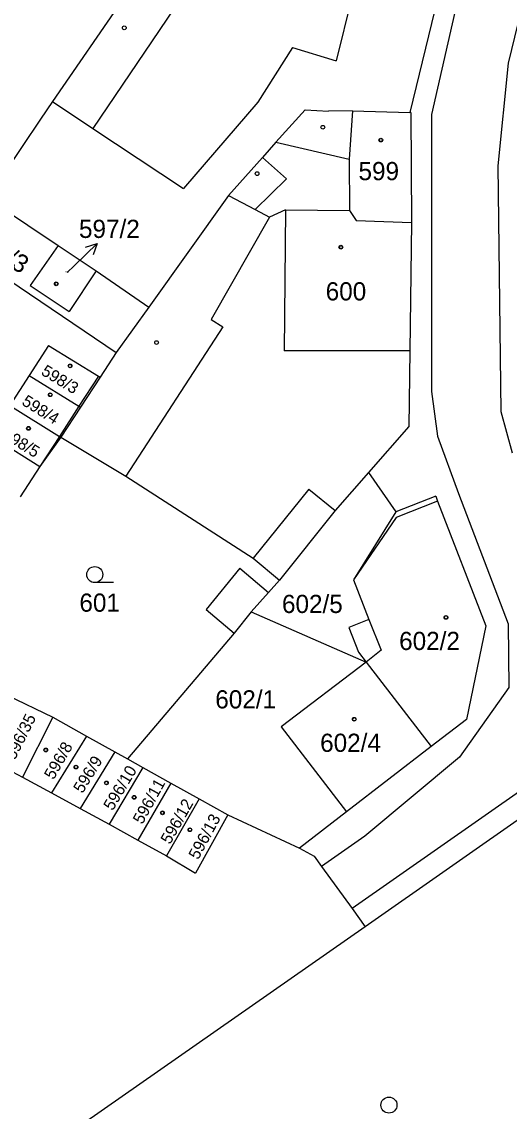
# Model space of a CAD drawing. Extents: x -593183 to -588034, y -1130415 to -1124994.
# Drawn here: x -591118.2 to -591072.6, y -1128787.1 to -1128685.3 of the extents above; entities that cross this region are included whole.
import ezdxf

# ---------------------------------------------------------------- set-up
doc = ezdxf.new("R2010")
doc.units = 0
for name, color, linetype in [('Vrstva 1', 7, 'Continuous'), ('Vrstva 16', 7, 'Continuous'), ('Vrstva 18', 7, 'Continuous'), ('Vrstva 19', 7, 'Continuous'), ('Vrstva 25', 7, 'Continuous'), ('Vrstva 4', 7, 'Continuous')]:
    doc.layers.add(name, color=color, linetype=linetype)

msp = doc.modelspace()

# ---------------------------------------------------------------- linework, layer by layer
at = {"layer": 'Vrstva 1'}
for p, q in [((-591074.25, -1128662.36), (-591081.86, -1128693.73)), ((-591105.59, -1128678.63), (-591115.3, -1128692.72)), ((-591115.3, -1128692.72), (-591116.41, -1128694.38)), ((-591116.41, -1128694.38), (-591119.84, -1128699.47)), ((-591091.64, -1128693.48), (-591094.38, -1128696.53)), ((-591091.64, -1128693.48), (-591089.48, -1128693.63)), ((-591087.23, -1128693.59), (-591089.48, -1128693.63)), ((-591087.23, -1128693.59), (-591081.86, -1128693.73)), ((-591081.76, -1128693.73), (-591081.86, -1128693.73)), ((-591081.76, -1128693.73), (-591081.71, -1128704.03)), ((-591094.38, -1128696.53), (-591095.65, -1128697.95)), ((-591095.65, -1128697.95), (-591098.83, -1128701.49)), ((-591098.83, -1128701.49), (-591106.26, -1128711.94)), ((-591098.83, -1128701.49), (-591096.34, -1128702.82)), ((-591121.38, -1128701.75), (-591114.77, -1128706.18)), ((-591096.34, -1128702.82), (-591094.99, -1128703.54)), ((-591093.49, -1128702.85), (-591094.99, -1128703.54)), ((-591093.49, -1128702.85), (-591087.51, -1128702.91)), ((-591087.51, -1128702.91), (-591086.87, -1128703.83)), ((-591086.87, -1128703.83), (-591081.71, -1128704.03)), ((-591081.71, -1128704.03), (-591081.85, -1128716.01)), ((-591124.56, -1128705.88), (-591109.32, -1128716.18)), ((-591114.77, -1128706.18), (-591117.38, -1128709.9)), ((-591114.77, -1128706.18), (-591111.2, -1128708.55)), ((-591111.2, -1128708.55), (-591113.74, -1128712.33)), ((-591111.2, -1128708.55), (-591106.26, -1128711.94)), ((-591117.38, -1128709.9), (-591113.74, -1128712.33)), ((-591106.26, -1128711.94), (-591109.32, -1128716.18)), ((-591115.66, -1128715.52), (-591117.48, -1128718.33)), ((-591115.66, -1128715.52), (-591110.99, -1128718.39)), ((-591109.32, -1128716.18), (-591110.82, -1128718.49)), ((-591081.85, -1128716.01), (-591081.96, -1128723.09)), ((-591117.48, -1128718.33), (-591119.28, -1128721.14)), ((-591117.48, -1128718.33), (-591112.81, -1128721.2)), ((-591110.82, -1128718.49), (-591112.67, -1128721.3)), ((-591110.99, -1128718.39), (-591110.82, -1128718.49)), ((-591119.28, -1128721.14), (-591114.64, -1128724.02)), ((-591112.67, -1128721.3), (-591114.51, -1128724.1)), ((-591112.81, -1128721.2), (-591112.67, -1128721.3)), ((-591081.96, -1128723.09), (-591085.71, -1128727.38)), ((-591121.09, -1128723.95), (-591116.47, -1128726.84)), ((-591114.51, -1128724.1), (-591116.47, -1128726.84)), ((-591114.64, -1128724.02), (-591114.51, -1128724.1)), ((-591114.51, -1128724.1), (-591108.43, -1128727.75)), ((-591116.47, -1128726.84), (-591118.3, -1128729.66)), ((-591108.43, -1128727.75), (-591096.5, -1128735.39)), ((-591085.71, -1128727.38), (-591088.84, -1128730.94)), ((-591085.71, -1128727.38), (-591083.17, -1128731.06)), ((-591079.44, -1128729.61), (-591083.17, -1128731.06)), ((-591079.44, -1128729.61), (-591079.26, -1128730.07)), ((-591088.84, -1128730.94), (-591094.06, -1128737.47)), ((-591083.17, -1128731.06), (-591087.14, -1128737.42)), ((-591079.26, -1128730.07), (-591074.74, -1128741.74)), ((-591096.5, -1128735.39), (-591094.06, -1128737.47)), ((-591094.06, -1128737.47), (-591095.09, -1128738.61)), ((-591087.14, -1128737.42), (-591085.7, -1128741.15)), ((-591095.09, -1128738.61), (-591096.69, -1128740.41)), ((-591096.69, -1128740.41), (-591098.3, -1128742.4)), ((-591096.69, -1128740.41), (-591085.94, -1128745.11)), ((-591085.7, -1128741.15), (-591087.56, -1128741.87)), ((-591087.56, -1128741.87), (-591086.66, -1128744.2)), ((-591074.74, -1128741.74), (-591076.56, -1128750.49)), ((-591098.3, -1128742.4), (-591108.28, -1128754.17)), ((-591086.66, -1128744.2), (-591085.94, -1128745.11)), ((-591085.94, -1128745.11), (-591093.89, -1128751.18)), ((-591085.94, -1128745.11), (-591079.86, -1128753.01)), ((-591119.52, -1128748.22), (-591115.27, -1128750.28)), ((-591115.27, -1128750.28), (-591118.08, -1128755.87)), ((-591115.27, -1128750.28), (-591112.12, -1128752.04)), ((-591093.89, -1128751.18), (-591087.79, -1128759.11)), ((-591076.56, -1128750.49), (-591079.86, -1128753.01)), ((-591112.12, -1128752.04), (-591115.39, -1128757.34)), ((-591112.12, -1128752.04), (-591109.45, -1128753.52)), ((-591079.86, -1128753.01), (-591087.79, -1128759.11)), ((-591122.36, -1128753.62), (-591118.08, -1128755.87)), ((-591109.45, -1128753.52), (-591112.69, -1128758.81)), ((-591109.45, -1128753.52), (-591108.28, -1128754.17)), ((-591108.28, -1128754.17), (-591106.83, -1128754.98)), ((-591106.83, -1128754.98), (-591110, -1128760.28)), ((-591106.83, -1128754.98), (-591104.21, -1128756.43)), ((-591118.08, -1128755.87), (-591115.39, -1128757.34)), ((-591104.21, -1128756.43), (-591107.3, -1128761.75)), ((-591104.21, -1128756.43), (-591101.58, -1128757.89)), ((-591115.39, -1128757.34), (-591112.69, -1128758.81)), ((-591101.58, -1128757.89), (-591104.61, -1128763.22)), ((-591101.58, -1128757.89), (-591098.87, -1128759.39)), ((-591068.59, -1128757.64), (-591086.03, -1128769.87)), ((-591112.69, -1128758.81), (-591110, -1128760.28)), ((-591098.87, -1128759.39), (-591101.9, -1128764.85)), ((-591098.87, -1128759.39), (-591092.18, -1128762.52)), ((-591087.79, -1128759.11), (-591092.18, -1128762.52)), ((-591110, -1128760.28), (-591107.3, -1128761.75)), ((-591107.3, -1128761.75), (-591104.61, -1128763.22)), ((-591092.18, -1128762.52), (-591090.81, -1128763.25)), ((-591104.61, -1128763.22), (-591101.9, -1128764.85)), ((-591090.81, -1128763.25), (-591090.11, -1128764.21)), ((-591090.11, -1128764.21), (-591087.26, -1128768.16)), ((-591087.26, -1128768.16), (-591086.03, -1128769.87)), ((-591086.03, -1128769.87), (-591115.27, -1128790.24))]:
    msp.add_line(p, q, dxfattribs=at)
at = {"layer": 'Vrstva 16'}
msp.add_line((-591113.9, -1128708.7), (-591113.27, -1128708.09), dxfattribs=at)
at = {"layer": 'Vrstva 25'}
for p, q in [((-591113.27, -1128708.09), (-591111.12, -1128706)), ((-591109.58, -1128737.69), (-591111.33, -1128737.69))]:
    msp.add_line(p, q, dxfattribs=at)
msp.add_lwpolyline([(-591112.19, -1128706.34), (-591111.12, -1128706), (-591111.49, -1128707.05)], dxfattribs=at)
for centre, radius in [((-591108.57, -1128685.83), 0.175), ((-591090, -1128695.12), 0.175), ((-591084.57, -1128696.32), 0.175), ((-591084.57, -1128696.32), 0.15), ((-591096.15, -1128699.46), 0.175), ((-591088.31, -1128706.33), 0.175), ((-591088.31, -1128706.33), 0.15), ((-591114.94, -1128709.76), 0.175), ((-591114.94, -1128709.76), 0.15), ((-591105.55, -1128715.25), 0.175), ((-591113.64, -1128717.43), 0.175), ((-591113.64, -1128717.43), 0.15), ((-591115.5, -1128720.13), 0.175), ((-591115.5, -1128720.13), 0.15), ((-591117.53, -1128723.27), 0.175), ((-591117.53, -1128723.27), 0.15), ((-591111.33, -1128736.94), 0.75), ((-591078.48, -1128740.94), 0.175), ((-591078.48, -1128740.94), 0.15), ((-591087.06, -1128750.46), 0.175), ((-591087.06, -1128750.46), 0.15), ((-591115.92, -1128753.33), 0.175), ((-591115.92, -1128753.33), 0.15), ((-591113.09, -1128754.93), 0.175), ((-591113.09, -1128754.93), 0.15), ((-591110.24, -1128756.41), 0.175), ((-591110.24, -1128756.41), 0.15), ((-591107.65, -1128757.76), 0.175), ((-591107.65, -1128757.76), 0.15), ((-591105, -1128759.21), 0.175), ((-591105, -1128759.21), 0.15), ((-591102.43, -1128760.79), 0.175), ((-591102.43, -1128760.79), 0.15), ((-591083.81, -1128786.53), 0.75)]:
    msp.add_circle(centre, radius, dxfattribs=at)
at = {"layer": 'Vrstva 4'}
for p, q in [((-591072.68, -1128662.56), (-591079.82, -1128693.92)), ((-591084.79, -1128672.91), (-591088.76, -1128688.92)), ((-591069.97, -1128678.15), (-591072.66, -1128689.13)), ((-591102.03, -1128681.23), (-591111.51, -1128695.23)), ((-591092.83, -1128687.67), (-591096.08, -1128692.79)), ((-591092.83, -1128687.67), (-591088.76, -1128688.92)), ((-591072.66, -1128689.13), (-591073.64, -1128698.72)), ((-591115.3, -1128692.72), (-591111.51, -1128695.23)), ((-591096.08, -1128692.79), (-591103.04, -1128700.84)), ((-591087.23, -1128693.59), (-591087.52, -1128698.11)), ((-591079.82, -1128693.92), (-591079.84, -1128719.83)), ((-591111.51, -1128695.23), (-591103.04, -1128700.84)), ((-591094.38, -1128696.53), (-591087.52, -1128698.11)), ((-591095.65, -1128697.95), (-591093.4, -1128699.93)), ((-591087.52, -1128698.11), (-591087.51, -1128702.91)), ((-591073.64, -1128698.72), (-591073.36, -1128721.7)), ((-591093.4, -1128699.93), (-591096.34, -1128702.82)), ((-591094.99, -1128703.54), (-591100.44, -1128713.1)), ((-591093.49, -1128702.85), (-591093.61, -1128716.03)), ((-591100.44, -1128713.1), (-591099.36, -1128713.78)), ((-591099.36, -1128713.78), (-591108.43, -1128727.75)), ((-591081.85, -1128716.01), (-591093.61, -1128716.03)), ((-591110.99, -1128718.39), (-591112.81, -1128721.2)), ((-591079.84, -1128719.83), (-591079.27, -1128724.01)), ((-591112.81, -1128721.2), (-591114.64, -1128724.02)), ((-591073.36, -1128721.7), (-591072.29, -1128725.56)), ((-591114.64, -1128724.02), (-591116.47, -1128726.84)), ((-591079.27, -1128724.01), (-591077.3, -1128729.36)), ((-591091.32, -1128728.95), (-591096.5, -1128735.39)), ((-591091.32, -1128728.95), (-591088.84, -1128730.94)), ((-591077.3, -1128729.36), (-591072.67, -1128741.55)), ((-591079.26, -1128730.07), (-591083.14, -1128731.61)), ((-591083.14, -1128731.61), (-591087.14, -1128737.42)), ((-591097.76, -1128736.34), (-591100.9, -1128740.2)), ((-591097.76, -1128736.34), (-591095.09, -1128738.61)), ((-591100.9, -1128740.2), (-591098.3, -1128742.4)), ((-591085.7, -1128741.15), (-591084.53, -1128743.99)), ((-591072.67, -1128741.55), (-591072.61, -1128747.5)), ((-591084.53, -1128743.99), (-591085.94, -1128745.11)), ((-591072.61, -1128747.5), (-591077.22, -1128754.02)), ((-591077.22, -1128754.02), (-591086.08, -1128761.4)), ((-591070.96, -1128756.78), (-591087.26, -1128768.16)), ((-591086.08, -1128761.4), (-591090.11, -1128764.21))]:
    msp.add_line(p, q, dxfattribs=at)

# ---------------------------------------------------------------- texts
at = {"layer": 'Vrstva 16'}
msp.add_text('597/2', height=1.7, dxfattribs=at).set_placement((-591112.81, -1128705.47))
at = {"layer": 'Vrstva 18'}
for s, p in [('601', (-591112.77, -1128740.41)), ('602/5', (-591093.82, -1128740.53)), ('602/1', (-591100.06, -1128749.45))]:
    msp.add_text(s, height=1.7, dxfattribs=at).set_placement(p)
at = {"layer": 'Vrstva 19'}
for s, height, p in [('599', 1.7, (-591086.66, -1128700.07)), ('597/2', 0.1, (-591114.08, -1128708.7)), ('600', 1.7, (-591089.73, -1128711.31)), ('602/2', 1.7, (-591082.86, -1128743.99)), ('602/4', 1.7, (-591090.25, -1128753.51))]:
    msp.add_text(s, height=height, dxfattribs=at).set_placement(p)
for s, height, rotation, p in [('597/3', 1.7, 327.6043, (-591123.01, -1128705.83)), ('598/3', 1.1, 328.7551, (-591116.43, -1128718.2)), ('598/4', 1.1, 328.3655, (-591118.24, -1128721.01)), ('598/5', 1.1, 328.5057, (-591120.06, -1128724.13)), ('596/35', 1.1, 63.3121, (-591118.81, -1128754.33)), ('596/8', 1.1, 60.0197, (-591115.19, -1128756.18)), ('596/9', 1.1, 58.5135, (-591112.48, -1128757.46)), ('596/10', 1.1, 59.1158, (-591109.66, -1128759.08)), ('596/11', 1.1, 61.0159, (-591106.88, -1128760.35)), ('596/12', 1.1, 60.3826, (-591104.29, -1128762.22)), ('596/13', 1.1, 61.663, (-591101.66, -1128763.66))]:
    msp.add_text(s, height=height, rotation=rotation, dxfattribs=at).set_placement(p)

doc.saveas('drawing.dxf')
